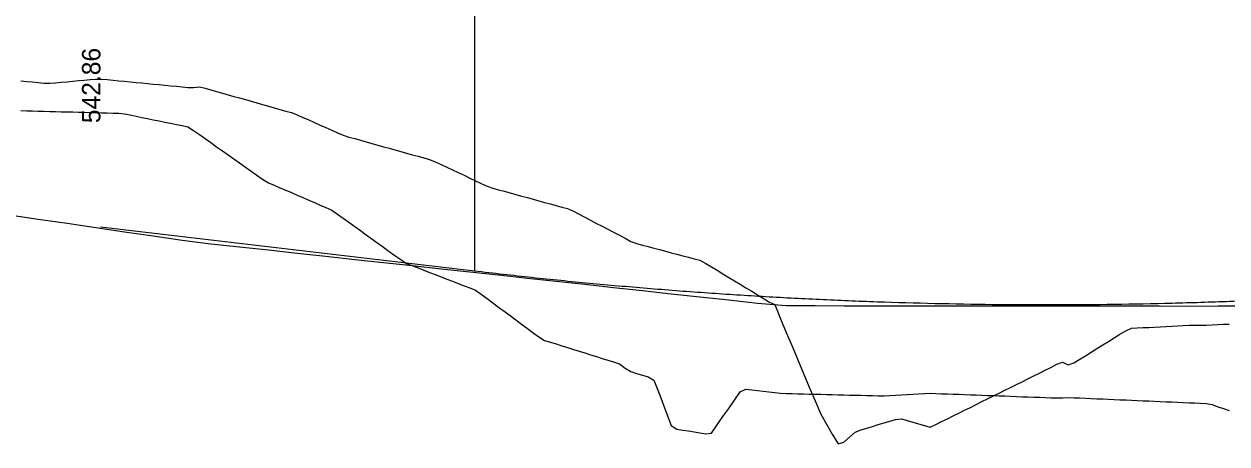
# Model space of a CAD drawing. Extents: x 1733822 to 1737718, y 1214897 to 1219897.
# Drawn here: x 1735191.5 to 1735400.6, y 1218287.5 to 1218360.6 of the extents above; entities that cross this region are included whole.
import ezdxf

# ---------------------------------------------------------------- set-up
doc = ezdxf.new("R2010")
doc.units = 0
for name, color, linetype in [('RD_DDB_Profile_EX', 7, 'Continuous'), ('RD_DDB_Profile_Lbl', 7, 'Continuous'), ('RD_DDB_Profile_PR', 7, 'Continuous'), ('RD_DDB_VCLbl', 7, 'Continuous'), ('RD_Sketch1', 7, 'Continuous'), ('RD_Sketch2', 7, 'Continuous')]:
    doc.layers.add(name, color=color, linetype=linetype)

msp = doc.modelspace()

# ---------------------------------------------------------------- linework, layer by layer
at = {"layer": 'RD_DDB_Profile_EX'}
msp.add_lwpolyline([(1735188.97, 1218327.38), (1735193.97, 1218326.65), (1735198.97, 1218325.91), (1735203.97, 1218325.18), (1735208.97, 1218324.44), (1735213.97, 1218323.71), (1735218.97, 1218322.97), (1735223.97, 1218322.35), (1735228.97, 1218321.81), (1735233.97, 1218321.27), (1735238.97, 1218320.72), (1735243.97, 1218320.18), (1735248.97, 1218319.64), (1735253.97, 1218319.1), (1735258.97, 1218318.56), (1735263.97, 1218318.01), (1735268.97, 1218317.47), (1735273.97, 1218316.93), (1735278.97, 1218316.39), (1735283.97, 1218315.85), (1735288.97, 1218315.3), (1735293.97, 1218314.76), (1735298.97, 1218314.21), (1735303.97, 1218313.67), (1735308.97, 1218313.12), (1735313.97, 1218312.58), (1735318.97, 1218312.03), (1735323.97, 1218311.61), (1735328.97, 1218311.6), (1735333.97, 1218311.58), (1735338.97, 1218311.57), (1735343.97, 1218311.56), (1735348.97, 1218311.57), (1735353.97, 1218311.56), (1735358.97, 1218311.55), (1735363.97, 1218311.54), (1735368.97, 1218311.53), (1735373.97, 1218311.55), (1735378.97, 1218311.54), (1735383.97, 1218311.53), (1735388.97, 1218311.53), (1735393.97, 1218311.52), (1735398.97, 1218311.55), (1735403.97, 1218311.54)], dxfattribs=at)
at = {"layer": 'RD_DDB_Profile_PR'}
msp.add_line((1735204.77, 1218325.32), (1735269.77, 1218317.64), dxfattribs=at)
msp.add_spline([(1735269.77, 1218317.64), (1735279.77, 1218316.52), (1735289.77, 1218315.51), (1735299.77, 1218314.63), (1735309.77, 1218313.86), (1735319.77, 1218313.22), (1735329.77, 1218312.69), (1735339.77, 1218312.28), (1735349.77, 1218311.99), (1735359.77, 1218311.81), (1735369.77, 1218311.76), (1735379.77, 1218311.83), (1735389.77, 1218312.01), (1735399.77, 1218312.31), (1735409.77, 1218312.74), (1735419.77, 1218313.28), (1735429.77, 1218313.94), (1735439.77, 1218314.72), (1735449.77, 1218315.61), (1735459.77, 1218316.63), (1735469.77, 1218317.76), (1735479.77, 1218319.02), (1735489.77, 1218320.39), (1735499.77, 1218321.88), (1735509.77, 1218323.49), (1735519.77, 1218325.22), (1735529.77, 1218327.07), (1735539.77, 1218329.04), (1735549.77, 1218331.12), (1735559.77, 1218333.33), (1735569.77, 1218335.65), (1735579.77, 1218338.09), (1735589.77, 1218340.65), (1735599.77, 1218343.33), (1735609.77, 1218346.13), (1735619.77, 1218349.05), (1735629.77, 1218352.08), (1735639.77, 1218355.24), (1735649.77, 1218358.51), (1735659.77, 1218361.9), (1735669.77, 1218365.41), (1735679.77, 1218369.04), (1735689.77, 1218372.79), (1735699.77, 1218376.66), (1735709.77, 1218380.65), (1735719.77, 1218384.75), (1735729.77, 1218388.98), (1735739.77, 1218393.32), (1735749.77, 1218397.78), (1735759.77, 1218402.36), (1735769.77, 1218407.06)], degree=3, dxfattribs=at)
at = {"layer": 'RD_DDB_VCLbl'}
msp.add_line((1735269.77, 1218512.06), (1735269.77, 1218317.64), dxfattribs=at)
at = {"layer": 'RD_Sketch1'}
for points in [[(1735190.97, 1218345.49), (1735191.97, 1218345.47), (1735192.97, 1218345.44), (1735193.97, 1218345.41), (1735194.97, 1218345.39), (1735195.97, 1218345.36), (1735196.97, 1218345.34), (1735197.97, 1218345.31), (1735198.97, 1218345.28), (1735199.97, 1218345.26), (1735200.97, 1218345.23), (1735201.97, 1218345.21), (1735202.97, 1218345.18), (1735203.97, 1218345.15), (1735204.97, 1218345.13), (1735205.97, 1218345.1), (1735206.97, 1218345.08), (1735207.97, 1218345.05), (1735208.97, 1218344.95), (1735209.97, 1218344.75), (1735210.97, 1218344.54), (1735211.97, 1218344.33), (1735212.97, 1218344.13), (1735213.97, 1218343.92), (1735214.97, 1218343.72), (1735215.97, 1218343.51)], [(1735215.97, 1218343.51), (1735216.97, 1218343.31), (1735217.97, 1218343.1), (1735218.97, 1218342.89), (1735219.97, 1218342.69), (1735220.97, 1218342.05), (1735221.97, 1218341.35), (1735222.97, 1218340.64), (1735223.97, 1218339.93), (1735224.97, 1218339.23), (1735225.97, 1218338.52), (1735226.97, 1218337.81), (1735227.97, 1218337.11), (1735228.97, 1218336.4), (1735229.97, 1218335.69), (1735230.97, 1218334.99), (1735231.97, 1218334.28), (1735232.97, 1218333.57), (1735233.97, 1218332.97), (1735234.97, 1218332.54), (1735235.97, 1218332.1), (1735236.97, 1218331.67), (1735237.97, 1218331.24), (1735238.97, 1218330.81), (1735239.97, 1218330.37), (1735240.97, 1218329.94), (1735241.97, 1218329.51), (1735242.97, 1218329.08), (1735243.97, 1218328.64), (1735244.97, 1218328.21), (1735245.97, 1218327.52), (1735246.97, 1218326.8), (1735247.97, 1218326.08), (1735248.97, 1218325.36), (1735249.97, 1218324.63), (1735250.97, 1218323.91), (1735251.97, 1218323.19), (1735252.97, 1218322.47), (1735253.97, 1218321.75), (1735254.97, 1218321.03), (1735255.97, 1218320.31), (1735256.97, 1218319.59), (1735257.97, 1218318.92), (1735258.97, 1218318.54), (1735259.97, 1218318.15), (1735260.97, 1218317.76), (1735261.97, 1218317.38), (1735262.97, 1218316.99), (1735263.97, 1218316.6), (1735264.97, 1218316.22), (1735265.97, 1218315.83), (1735266.97, 1218315.45), (1735267.97, 1218315.06), (1735268.97, 1218314.67), (1735269.97, 1218314.29), (1735270.97, 1218313.57), (1735271.97, 1218312.83), (1735272.97, 1218312.09), (1735273.97, 1218311.34), (1735274.97, 1218310.6), (1735275.97, 1218309.86), (1735276.97, 1218309.12), (1735277.97, 1218308.38), (1735278.97, 1218307.64), (1735279.97, 1218306.89), (1735280.97, 1218306.15), (1735281.97, 1218305.55), (1735282.97, 1218305.24), (1735283.97, 1218304.93), (1735284.97, 1218304.61), (1735285.97, 1218304.3), (1735286.97, 1218303.99), (1735287.97, 1218303.68), (1735288.97, 1218303.36), (1735289.97, 1218303.05), (1735290.97, 1218302.74), (1735291.97, 1218302.42), (1735292.97, 1218302.11), (1735293.97, 1218301.8), (1735294.97, 1218301.49), (1735295.97, 1218300.74), (1735296.97, 1218300.11), (1735297.97, 1218299.81), (1735298.97, 1218299.52), (1735299.97, 1218299.22), (1735300.97, 1218298.64), (1735301.97, 1218296.01), (1735302.97, 1218293.38), (1735303.97, 1218290.76), (1735304.97, 1218290.13), (1735305.97, 1218289.96), (1735306.97, 1218289.8), (1735307.97, 1218289.64), (1735308.97, 1218289.48), (1735309.97, 1218289.31), (1735310.97, 1218289.43), (1735311.97, 1218290.86), (1735312.97, 1218292.3), (1735313.97, 1218293.73), (1735314.97, 1218295.17), (1735315.97, 1218296.6)], [(1735315.97, 1218296.6), (1735316.97, 1218297.05), (1735317.97, 1218296.94), (1735318.97, 1218296.83), (1735319.97, 1218296.72), (1735320.97, 1218296.6), (1735321.97, 1218296.49), (1735322.97, 1218296.38), (1735323.97, 1218296.31), (1735324.97, 1218296.29), (1735325.97, 1218296.26), (1735326.97, 1218296.24), (1735327.97, 1218296.22), (1735328.97, 1218296.19), (1735329.97, 1218296.17), (1735330.97, 1218296.15), (1735331.97, 1218296.12), (1735332.97, 1218296.1), (1735333.97, 1218296.07), (1735334.97, 1218296.05), (1735335.97, 1218296.03), (1735336.97, 1218296), (1735337.97, 1218295.98), (1735338.97, 1218295.96), (1735339.97, 1218295.93), (1735340.97, 1218295.91), (1735341.97, 1218295.98), (1735342.97, 1218296.04), (1735343.97, 1218296.1), (1735344.97, 1218296.16), (1735345.97, 1218296.22), (1735346.97, 1218296.28), (1735347.97, 1218296.34), (1735348.97, 1218296.36), (1735349.97, 1218296.32), (1735350.97, 1218296.28), (1735351.97, 1218296.25), (1735352.97, 1218296.21), (1735353.97, 1218296.17), (1735354.97, 1218296.13), (1735355.97, 1218296.1), (1735356.97, 1218296.06), (1735357.97, 1218296.02), (1735358.97, 1218295.99), (1735359.97, 1218295.95), (1735360.97, 1218295.91), (1735361.97, 1218295.88), (1735362.97, 1218295.84), (1735363.97, 1218295.8), (1735364.97, 1218295.76), (1735365.97, 1218295.73), (1735366.97, 1218295.69), (1735367.97, 1218295.65), (1735368.97, 1218295.62), (1735369.97, 1218295.58), (1735370.97, 1218295.55), (1735371.97, 1218295.57), (1735372.97, 1218295.59), (1735373.97, 1218295.58), (1735374.97, 1218295.54), (1735375.97, 1218295.49), (1735376.97, 1218295.45), (1735377.97, 1218295.41), (1735378.97, 1218295.36), (1735379.97, 1218295.32), (1735380.97, 1218295.28), (1735381.97, 1218295.23), (1735382.97, 1218295.19), (1735383.97, 1218295.15), (1735384.97, 1218295.1), (1735385.97, 1218295.06), (1735386.97, 1218295.02), (1735387.97, 1218294.97), (1735388.97, 1218294.93), (1735389.97, 1218294.89), (1735390.97, 1218294.84), (1735391.97, 1218294.8), (1735392.97, 1218294.76), (1735393.97, 1218294.71), (1735394.97, 1218294.67), (1735395.97, 1218294.63), (1735396.97, 1218294.58), (1735397.97, 1218294.39), (1735398.97, 1218294.02), (1735399.97, 1218293.7), (1735400.97, 1218293.38)]]:
    msp.add_lwpolyline(points, dxfattribs=at)
at = {"layer": 'RD_Sketch2'}
for points in [[(1735190.97, 1218350.68), (1735191.97, 1218350.58), (1735192.97, 1218350.48), (1735193.97, 1218350.39), (1735194.97, 1218350.29), (1735195.97, 1218350.25), (1735196.97, 1218350.34), (1735197.97, 1218350.43), (1735198.97, 1218350.52), (1735199.97, 1218350.61), (1735200.97, 1218350.71), (1735201.97, 1218350.8), (1735202.97, 1218350.89), (1735203.97, 1218350.98), (1735204.97, 1218350.99), (1735205.97, 1218350.89), (1735206.97, 1218350.79), (1735207.97, 1218350.7), (1735208.97, 1218350.6), (1735209.97, 1218350.5), (1735210.97, 1218350.41), (1735211.97, 1218350.31), (1735212.97, 1218350.21), (1735213.97, 1218350.12)], [(1735213.97, 1218350.12), (1735214.97, 1218350.02), (1735215.97, 1218349.93), (1735216.97, 1218349.83), (1735217.97, 1218349.73), (1735218.97, 1218349.64), (1735219.97, 1218349.54), (1735220.97, 1218349.53), (1735221.97, 1218349.64), (1735222.97, 1218349.4), (1735223.97, 1218349.11), (1735224.97, 1218348.83), (1735225.97, 1218348.55), (1735226.97, 1218348.26), (1735227.97, 1218347.98), (1735228.97, 1218347.7), (1735229.97, 1218347.41), (1735230.97, 1218347.13), (1735231.97, 1218346.85), (1735232.97, 1218346.56), (1735233.97, 1218346.28), (1735234.97, 1218346), (1735235.97, 1218345.71), (1735236.97, 1218345.43), (1735237.97, 1218345.15), (1735238.97, 1218344.77), (1735239.97, 1218344.32), (1735240.97, 1218343.88), (1735241.97, 1218343.43), (1735242.97, 1218342.99), (1735243.97, 1218342.55), (1735244.97, 1218342.1), (1735245.97, 1218341.66), (1735246.97, 1218341.22), (1735247.97, 1218340.91), (1735248.97, 1218340.63), (1735249.97, 1218340.35), (1735250.97, 1218340.07), (1735251.97, 1218339.79), (1735252.97, 1218339.51), (1735253.97, 1218339.23), (1735254.97, 1218338.95), (1735255.97, 1218338.67), (1735256.97, 1218338.39), (1735257.97, 1218338.11), (1735258.97, 1218337.83), (1735259.97, 1218337.55), (1735260.97, 1218337.28), (1735261.97, 1218337), (1735262.97, 1218336.62), (1735263.97, 1218336.14), (1735264.97, 1218335.67), (1735265.97, 1218335.2), (1735266.97, 1218334.72), (1735267.97, 1218334.25), (1735268.97, 1218333.77), (1735269.97, 1218333.3), (1735270.97, 1218332.82), (1735271.97, 1218332.35), (1735272.97, 1218332.02), (1735273.97, 1218331.75), (1735274.97, 1218331.47), (1735275.97, 1218331.2), (1735276.97, 1218330.93), (1735277.97, 1218330.65), (1735278.97, 1218330.38), (1735279.97, 1218330.1), (1735280.97, 1218329.83), (1735281.97, 1218329.55), (1735282.97, 1218329.28), (1735283.97, 1218329.01), (1735284.97, 1218328.73), (1735285.97, 1218328.46), (1735286.97, 1218327.99), (1735287.97, 1218327.47), (1735288.97, 1218326.95), (1735289.97, 1218326.43), (1735290.97, 1218325.9), (1735291.97, 1218325.38), (1735292.97, 1218324.86), (1735293.97, 1218324.34), (1735294.97, 1218323.82), (1735295.97, 1218323.3), (1735296.97, 1218322.77), (1735297.97, 1218322.39), (1735298.97, 1218322.13), (1735299.97, 1218321.86), (1735300.97, 1218321.6), (1735301.97, 1218321.33), (1735302.97, 1218321.07), (1735303.97, 1218320.8), (1735304.97, 1218320.53), (1735305.97, 1218320.27), (1735306.97, 1218320), (1735307.97, 1218319.74), (1735308.97, 1218319.47), (1735309.97, 1218318.94), (1735310.97, 1218318.33), (1735311.97, 1218317.73), (1735312.97, 1218317.12), (1735313.97, 1218316.51)], [(1735313.97, 1218316.51), (1735314.97, 1218315.91), (1735315.97, 1218315.3), (1735316.97, 1218314.69), (1735317.97, 1218314.09), (1735318.97, 1218313.48), (1735319.97, 1218312.87), (1735320.97, 1218312.27), (1735321.97, 1218311.78), (1735322.97, 1218309.32), (1735323.97, 1218306.94), (1735324.97, 1218304.56), (1735325.97, 1218302.18), (1735326.97, 1218299.8), (1735327.97, 1218297.42), (1735328.97, 1218295.04), (1735329.97, 1218292.7), (1735330.97, 1218290.98), (1735331.97, 1218289.26), (1735332.97, 1218287.54), (1735333.97, 1218287.88), (1735334.97, 1218288.73), (1735335.97, 1218289.58), (1735336.97, 1218289.98), (1735337.97, 1218290.29), (1735338.97, 1218290.6), (1735339.97, 1218290.9), (1735340.97, 1218291.21), (1735341.97, 1218291.52), (1735342.97, 1218291.82), (1735343.97, 1218291.88), (1735344.97, 1218291.59), (1735345.97, 1218291.31), (1735346.97, 1218291.02), (1735347.97, 1218290.73), (1735348.97, 1218290.45), (1735349.97, 1218290.92), (1735350.97, 1218291.42), (1735351.97, 1218291.92), (1735352.97, 1218292.41), (1735353.97, 1218292.91), (1735354.97, 1218293.41), (1735355.97, 1218293.9), (1735356.97, 1218294.4), (1735357.97, 1218294.9), (1735358.97, 1218295.39), (1735359.97, 1218295.89), (1735360.97, 1218296.39), (1735361.97, 1218296.88), (1735362.97, 1218297.38), (1735363.97, 1218297.88), (1735364.97, 1218298.37), (1735365.97, 1218298.87), (1735366.97, 1218299.37), (1735367.97, 1218299.86), (1735368.97, 1218300.36), (1735369.97, 1218300.86), (1735370.97, 1218301.4), (1735371.97, 1218301.75), (1735372.97, 1218301.27), (1735373.97, 1218301.65), (1735374.97, 1218302.27), (1735375.97, 1218302.89), (1735376.97, 1218303.51), (1735377.97, 1218304.13), (1735378.97, 1218304.75), (1735379.97, 1218305.37), (1735380.97, 1218305.99), (1735381.97, 1218306.61), (1735382.97, 1218307.23), (1735383.97, 1218307.65), (1735384.97, 1218307.71), (1735385.97, 1218307.76), (1735386.97, 1218307.81), (1735387.97, 1218307.87), (1735388.97, 1218307.92), (1735389.97, 1218307.97), (1735390.97, 1218308.03), (1735391.97, 1218308.08), (1735392.97, 1218308.14), (1735393.97, 1218308.19), (1735394.97, 1218308.2), (1735395.97, 1218308.21), (1735396.97, 1218308.22), (1735397.97, 1218308.25), (1735398.97, 1218308.29), (1735399.97, 1218308.34), (1735400.97, 1218308.38)]]:
    msp.add_lwpolyline(points, dxfattribs=at)

# ---------------------------------------------------------------- texts
at = {"layer": 'RD_DDB_Profile_Lbl'}
msp.add_text('542.86', height=3.2, rotation=90, dxfattribs=at).set_placement((1735204.77, 1218343.32))

doc.saveas('drawing.dxf')
